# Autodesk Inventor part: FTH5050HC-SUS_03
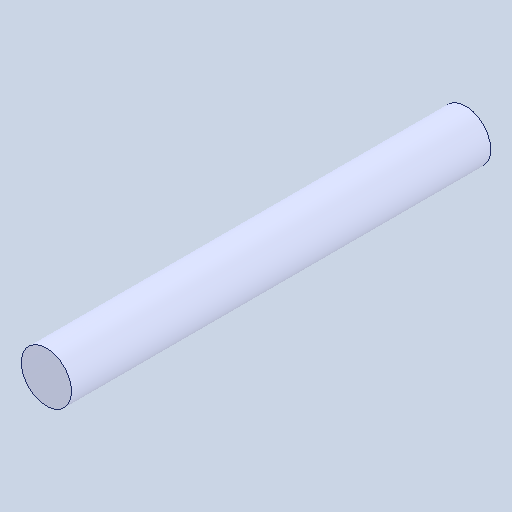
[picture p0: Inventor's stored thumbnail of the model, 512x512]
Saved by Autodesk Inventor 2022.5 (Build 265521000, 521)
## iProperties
Created: 2024-08
Part Number: FTH5050HC-SUS_03
Material: 一般
Document SubType Name: Modeling
Designer: ImaoCorp
Density: 1 g/cm^3
Appearance: 既定
Author: ImaoCorp
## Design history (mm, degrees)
feature "FTH5050HC-SUS_03"
node "ソリッド1"
